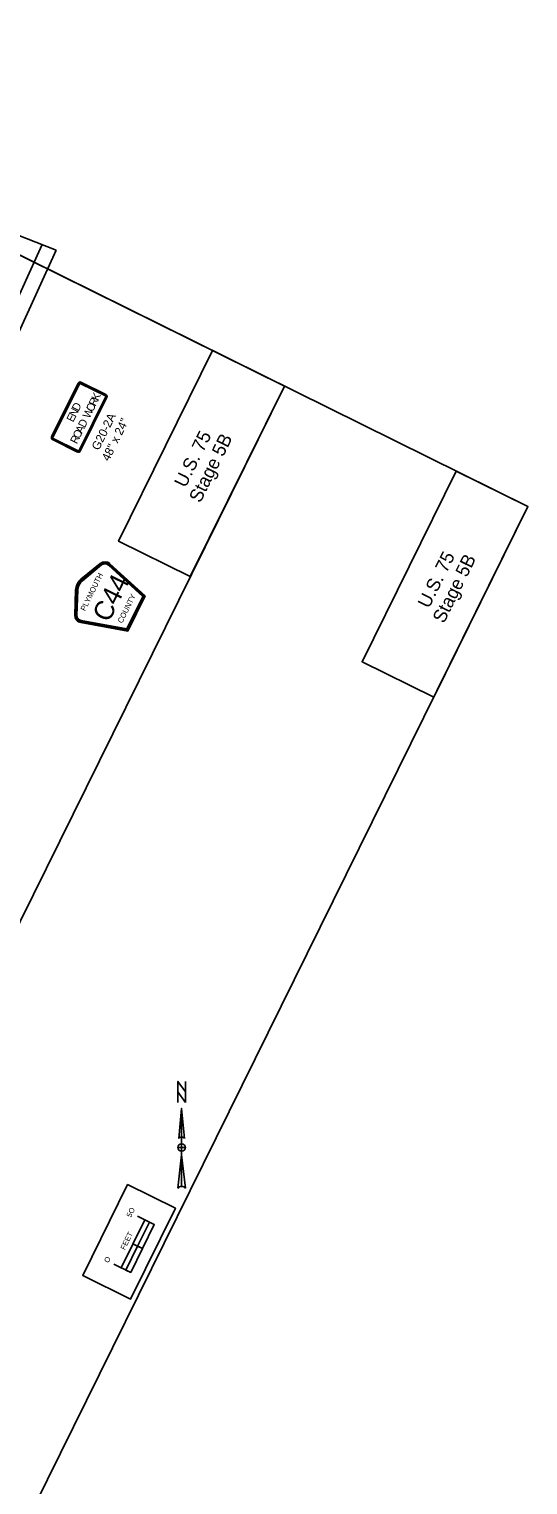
# Model space of a CAD drawing. Extents: x 14104283 to 14128447, y 8633203 to 8671666.
# Drawn here: x 14120414 to 14120882, y 8670301 to 8671666 of the extents above; entities that cross this region are included whole.
import ezdxf

# ---------------------------------------------------------------- set-up
doc = ezdxf.new("R2010")
doc.units = 0
for name, color, linetype in [('Cell', 7, 'Continuous'), ('Default', 7, 'Continuous'), ('dsnCellsNorthArrow', 7, 'Continuous'), ('dsnCellsScaleBlock', 7, 'Continuous'), ('dsnNonPlotable', 7, 'Continuous'), ('dsnPaintExistingBrokenLaneLineWhite', 7, 'Continuous'), ('dsnTextOverlapEven', 7, 'Continuous'), ('Sign', 7, 'Continuous')]:
    doc.layers.add(name, color=color, linetype=linetype)

msp = doc.modelspace()

# ---------------------------------------------------------------- linework, layer by layer
at = {"layer": 'Cell'}
for p, q in [((14120460.2, 8671333.9), (14120435.2, 8671283.5)), ((14120462.1, 8671333.6), (14120462.5, 8671334.3)), ((14120486.2, 8671323.1), (14120462.7, 8671334.7)), ((14120460.6, 8671333.7), (14120461.3, 8671333.3)), ((14120462.1, 8671270.2), (14120487, 8671320.6)), ((14120486, 8671322.7), (14120485.6, 8671322)), ((14120485.9, 8671321.2), (14120486.6, 8671320.8)), ((14120436.3, 8671282.9), (14120435.6, 8671283.3)), ((14120436.1, 8671281), (14120459.6, 8671269.3)), ((14120436.3, 8671281.4), (14120436.6, 8671282.1)), ((14120460.2, 8671270.4), (14120459.8, 8671269.7)), ((14120461.7, 8671270.4), (14120461, 8671270.7))]:
    msp.add_line(p, q, dxfattribs=at)
for points in [[(14120486, 8671322.7), (14120462.5, 8671334.3), (14120462.1, 8671333.6), (14120485.6, 8671322), (14120486, 8671322.7)], [(14120460.6, 8671333.7), (14120435.6, 8671283.3), (14120436.3, 8671282.9), (14120461.3, 8671333.3), (14120460.6, 8671333.7)], [(14120461.7, 8671270.4), (14120486.6, 8671320.8), (14120485.9, 8671321.2), (14120461, 8671270.7), (14120461.7, 8671270.4)], [(14120436.3, 8671281.4), (14120459.8, 8671269.7), (14120460.2, 8671270.4), (14120436.6, 8671282.1), (14120436.3, 8671281.4)]]:
    msp.add_lwpolyline(points, close=True, dxfattribs=at)
for centre, radius, start, end in [((14120461.8, 8671333.1), 1.87, 63.6912, 153.6914), ((14120461.8, 8671333.1), 1.41, 63.6912, 153.6914), ((14120461.8, 8671333.1), 0.625, 63.6912, 153.6914), ((14120485.4, 8671321.4), 0.625, 333.6912, 63.6914), ((14120485.4, 8671321.4), 1.41, 333.6912, 63.6914), ((14120485.4, 8671321.4), 1.87, 333.6912, 63.6914), ((14120436.9, 8671282.6), 1.87, 153.6914, 243.691), ((14120436.9, 8671282.6), 1.41, 153.6914, 243.691), ((14120436.9, 8671282.6), 0.625, 153.6914, 243.691), ((14120460.4, 8671271), 1.87, 243.691, 333.6912), ((14120460.4, 8671271), 1.41, 243.691, 333.6912), ((14120460.4, 8671271), 0.625, 243.691, 333.6912)]:
    msp.add_arc(centre, radius, start, end, dxfattribs=at)
at = {"layer": 'Default'}
for p, q in [((14120377.9, 8671482.5), (14120439.4, 8671458.6)), ((14120439.4, 8671458.6), (14120360.6, 8671285.8))]:
    msp.add_line(p, q, dxfattribs=at)
at = {"layer": 'dsnCellsNorthArrow'}
for p, q in [((14120557.2, 8670653.9), (14120560, 8670625.8)), ((14120557.2, 8670653.9), (14120557.2, 8670580.7)), ((14120554.4, 8670625.8), (14120554.4, 8670625.8)), ((14120554.5, 8670626), (14120555, 8670626.6)), ((14120557.2, 8670613.8), (14120557.2, 8670613.8)), ((14120553.7, 8670579.3), (14120557.2, 8670610.3))]:
    msp.add_line(p, q, dxfattribs=at)
msp.add_lwpolyline([(14120560.7, 8670659.6), (14120553.7, 8670669.4), (14120553.7, 8670679.3), (14120560.7, 8670669.4)], close=True, dxfattribs=at)
for points in [[(14120553.7, 8670659.6), (14120553.7, 8670679.3), (14120560.7, 8670669.4), (14120560.7, 8670679.3)], [(14120554.4, 8670625.8), (14120557.2, 8670653.9), (14120557.2, 8670627.2)], [(14120557.2, 8670613.8), (14120557.2, 8670617.3), (14120553.7, 8670617.3)], [(14120560.7, 8670617.3), (14120557.2, 8670617.3), (14120557.2, 8670620.8)], [(14120557.2, 8670580.7), (14120557.2, 8670610.3), (14120560.7, 8670579.3)]]:
    msp.add_lwpolyline(points, dxfattribs=at)
for centre, radius, start, end in [((14120557.2, 8670623.7), 3.52, 90.0204, 143.1257), ((14120557.2, 8670623.7), 3.52, 36.8481, 90.0218), ((14120557.2, 8670617.3), 3.52, 90, 180), ((14120557.2, 8670617.3), 3.52, 180, 270), ((14120557.2, 8670617.3), 3.52, 0, 90), ((14120557.2, 8670617.3), 3.52, 270, 360), ((14120557.2, 8670575.6), 5.1, 89.9894, 133.619), ((14120557.2, 8670575.6), 5.11, 46.4021, 90.0006)]:
    msp.add_arc(centre, radius, start, end, dxfattribs=at)
at = {"layer": 'dsnCellsScaleBlock'}
msp.add_line((14120520.5, 8670522.6), (14120511.5, 8670527), dxfattribs=at)
msp.add_line((14120520.5, 8670522.6), (14120511.5, 8670527), dxfattribs=at)
for points in [[(14120464.4, 8670497.3), (14120506.5, 8670582.5), (14120551.4, 8670560.3), (14120509.3, 8670475.2)], [(14120509.3, 8670475.2), (14120464.4, 8670497.3), (14120506.5, 8670582.5), (14120551.4, 8670560.3)], [(14120515.9, 8670524.8), (14120527, 8670547.3), (14120522.6, 8670549.5), (14120511.5, 8670527)], [(14120509.4, 8670500.2), (14120520.5, 8670522.6), (14120515.9, 8670524.8), (14120504.9, 8670502.4)]]:
    msp.add_lwpolyline(points, close=True, dxfattribs=at)
for points in [[(14120493.7, 8670508), (14120509.4, 8670500.2), (14120531.5, 8670545), (14120515.8, 8670552.8)], [(14120500.4, 8670504.6), (14120522.6, 8670549.5)]]:
    msp.add_lwpolyline(points, dxfattribs=at)
at = {"layer": 'dsnNonPlotable'}
for points in [[(14119282, 8670260.6), (14119976.8, 8671665.7), (14120882.2, 8671218.1), (14120187.4, 8669813)], [(14119506.2, 8670149.8), (14120200.9, 8671554.9), (14120653.6, 8671331.1), (14119958.8, 8669926)]]:
    msp.add_lwpolyline(points, close=True, dxfattribs=at)
at = {"layer": 'dsnPaintExistingBrokenLaneLineWhite'}
msp.add_line((14120347.5, 8671290.9), (14120426.4, 8671463.7), dxfattribs=at)
at = {"layer": 'dsnTextOverlapEven'}
for points in [[(14120653.6, 8671331.1), (14120565.3, 8671152.5), (14120498, 8671185.7), (14120586.3, 8671364.3)], [(14120498, 8671185.7), (14120586.3, 8671364.3), (14120653.6, 8671331.1), (14120565.3, 8671152.5)], [(14120882.2, 8671218.1), (14120793.8, 8671039.4), (14120726.6, 8671072.7), (14120814.9, 8671251.3)], [(14120726.6, 8671072.7), (14120814.9, 8671251.3), (14120882.2, 8671218.1), (14120793.8, 8671039.4)]]:
    msp.add_lwpolyline(points, close=True, dxfattribs=at)
at = {"layer": 'Sign'}
for p, q in [((14120462.7, 8671150), (14120480.8, 8671164.9)), ((14120481.4, 8671164.1), (14120463.3, 8671149.3)), ((14120463.3, 8671149.3), (14120481.4, 8671164.1)), ((14120464, 8671148.5), (14120482, 8671163.4)), ((14120482, 8671163.4), (14120464, 8671148.5)), ((14120488.6, 8671163.2), (14120520.7, 8671133.9)), ((14120520.7, 8671133.9), (14120488.6, 8671163.2)), ((14120521.9, 8671134.2), (14120489.3, 8671163.9)), ((14120489.3, 8671163.9), (14120521.9, 8671134.2)), ((14120489.9, 8671164.6), (14120523, 8671134.4)), ((14120456.9, 8671116.5), (14120457.7, 8671139.9)), ((14120458.7, 8671139.8), (14120457.8, 8671116.4)), ((14120457.8, 8671116.4), (14120458.7, 8671139.8)), ((14120458.8, 8671116.4), (14120459.7, 8671139.8)), ((14120459.7, 8671139.8), (14120458.8, 8671116.4)), ((14120520.7, 8671133.9), (14120505.7, 8671103.6)), ((14120505.7, 8671103.6), (14120520.7, 8671133.9)), ((14120506.2, 8671102.5), (14120521.9, 8671134.2)), ((14120521.9, 8671134.2), (14120506.2, 8671102.5)), ((14120523, 8671134.4), (14120506.7, 8671101.4)), ((14120523, 8671134.4), (14120521.9, 8671134.2)), ((14120506.7, 8671101.4), (14120462.6, 8671109.4)), ((14120462.8, 8671110.3), (14120506.2, 8671102.5)), ((14120506.2, 8671102.5), (14120462.8, 8671110.3)), ((14120505.7, 8671103.6), (14120462.9, 8671111.3)), ((14120462.9, 8671111.3), (14120505.7, 8671103.6)), ((14120505.7, 8671103.6), (14120506.2, 8671102.5))]:
    msp.add_line(p, q, dxfattribs=at)
for centre, radius, start, end in [((14120485.2, 8671159.5), 6.97, 47.5883, 129.4611), ((14120485.2, 8671159.5), 5.99, 47.5883, 129.4611), ((14120485.2, 8671159.5), 5.99, 47.5883, 129.4611), ((14120485.2, 8671159.5), 5.02, 47.5883, 129.4611), ((14120485.2, 8671159.5), 5.02, 47.5883, 129.4611), ((14120471.5, 8671139.4), 13.8, 129.4611, 177.9213), ((14120471.5, 8671139.4), 12.8, 129.4611, 177.9213), ((14120471.5, 8671139.4), 12.8, 129.4611, 177.9213), ((14120471.5, 8671139.4), 11.8, 129.4611, 177.9213), ((14120471.5, 8671139.4), 11.8, 129.4611, 177.9213), ((14120463.8, 8671116.2), 6.97, 177.9213, 259.7941), ((14120463.8, 8671116.2), 5.99, 177.9213, 259.7941), ((14120463.8, 8671116.2), 5.99, 177.9213, 259.7941), ((14120463.8, 8671116.2), 5.02, 177.9213, 259.7941), ((14120463.8, 8671116.2), 5.02, 177.9213, 259.7941)]:
    msp.add_arc(centre, radius, start, end, dxfattribs=at)

# ---------------------------------------------------------------- texts
at = {"layer": 'Cell'}
for s, height, p in [('R', 7.5, (14120476.3, 8671311.6)), ('K', 7.5, (14120478.8, 8671316.6)), ('N', 7.5, (14120457.7, 8671301.5)), ('D', 7.5, (14120460.4, 8671306.9)), ('W', 7.5, (14120470.6, 8671300.1)), ('O', 7.5, (14120473.7, 8671306.3)), ('E', 7.5, (14120455.4, 8671296.7)), ('A', 7.5, (14120463.7, 8671286.1)), ('D', 7.5, (14120466.3, 8671291.4)), ('G20-2A', 8, (14120479.4, 8671270.2)), ('48" x 24"', 8, (14120488.9, 8671260.1)), ('R', 7.5, (14120458.9, 8671276.3)), ('O', 7.5, (14120461.2, 8671281.1))]:
    msp.add_text(s, height=height, rotation=63.6912, dxfattribs=at).set_placement(p)
at = {"layer": 'dsnCellsScaleBlock'}
for s, p in [('5O', (14120509.6, 8670551.3)), ('FEET', (14120503.9, 8670520.8)), ('O', (14120488.5, 8670508.7))]:
    msp.add_text(s, height=5, rotation=63.6912, dxfattribs=at).set_placement(p)
at = {"layer": 'dsnTextOverlapEven'}
for s, p in [('U.S. 75', (14120560.8, 8671235.1)), ('Stage 5B', (14120574.7, 8671220.9)), ('U.S. 75', (14120789.3, 8671122)), ('Stage 5B', (14120803.3, 8671107.9))]:
    msp.add_text(s, height=12.5, rotation=63.6912, dxfattribs=at).set_placement(p)
at = {"layer": 'Sign'}
for s, height, p in [('PLYMOUTH', 5.18, (14120466.6, 8671119.8)), ('C44', 18.14, (14120488.9, 8671108.7)), ('COUNTY', 5.18, (14120501.4, 8671108.3))]:
    msp.add_text(s, height=height, rotation=63.6912, dxfattribs=at).set_placement(p)

doc.saveas('drawing.dxf')
